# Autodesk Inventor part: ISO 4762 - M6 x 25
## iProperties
IsCustomPart: 0
Created: 2007-11
Part Number: ISO 4762 - M6 x 25
Material: Stainless Steel, 440C
Description: Hexagon Socket Head Cap Screw
Document SubType Name: Modeling
Standard: ISO 4762
Designer: CM
Standard Revision: Fourth edition 2004-03-01
Standards Organization: ISO
Language: en-US
Size Designation: M6 x 25
Categories: <MemberInstance><Categories><Category DisplayName="Fasteners" InternalName="e4da775c-781d-43d5-af7c-5136215cf5a6" Mnemonic="FSTN"><Category DisplayName="Bolts"
Density: 7.75 g/cm^3
Mass: 8.47364 g
Surface Area: 8.58349 cm^2
Volume: 1.09337 cm^3
Author: CM
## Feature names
1. Body [Revolution]
2. Slot [Extrusion]
3. Fillet1
4. Chamfer1
5. Fillet2
